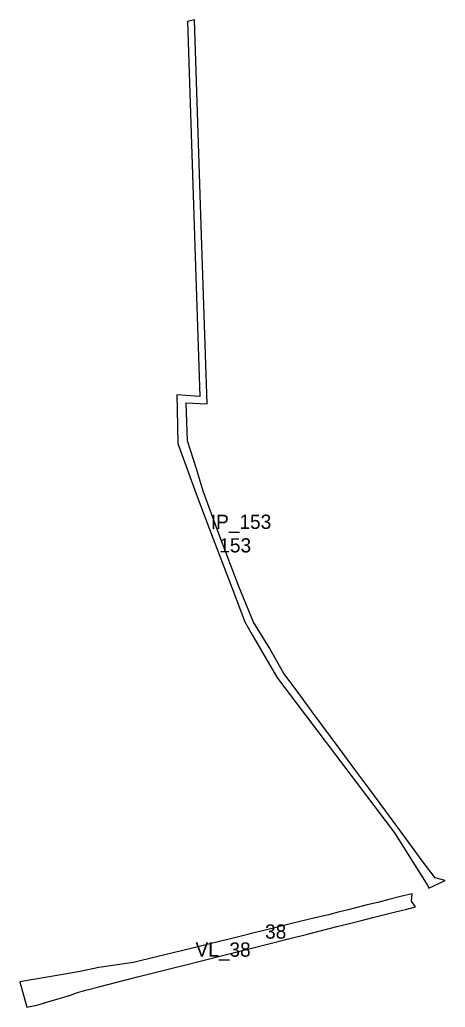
# Model space of a CAD drawing. Extents: x -521939 to -518034, y -1194984 to -1189555.
# Drawn here: x -519208 to -518909, y -1192540 to -1191848 of the extents above; entities that cross this region are included whole.
import ezdxf

# ---------------------------------------------------------------- set-up
doc = ezdxf.new("R2010")
doc.units = 0
doc.layers.add('96120023', color=7, linetype='Continuous')
doc.layers.add('ID VPS', color=7, linetype='Continuous')

msp = doc.modelspace()

# ---------------------------------------------------------------- linework, layer by layer
at = {"layer": '96120023'}
for points in [[(-519085.16, -1191847.79), (-519090.12, -1191848.97)], [(-519090.12, -1191848.97), (-519085.14, -1191999.24), (-519084.89, -1192006.65)], [(-519076.23, -1192117.14), (-519080.14, -1191999.07), (-519085.16, -1191847.79)], [(-519084.89, -1192006.65), (-519081.41, -1192111.82)], [(-519091.16, -1192111.23), (-519097.51, -1192110.84)], [(-519097.51, -1192110.84), (-519097.34, -1192121.07)], [(-519081.41, -1192111.82), (-519091.16, -1192111.23)], [(-519090.14, -1192143.06), (-519091, -1192116.25)], [(-519091, -1192116.25), (-519081.24, -1192116.84)], [(-519097.34, -1192121.07), (-519096.85, -1192144.75)], [(-519081.24, -1192116.84), (-519076.23, -1192117.14)], [(-519079.2, -1192178.33), (-519083.86, -1192162.62), (-519090.14, -1192143.06)], [(-519096.85, -1192144.75), (-519088.41, -1192167.96)], [(-519088.41, -1192167.96), (-519084.92, -1192177.56)], [(-519084.92, -1192177.56), (-519080.59, -1192189.45), (-519072.1, -1192211.71)], [(-519067.32, -1192210.12), (-519079.2, -1192178.33)], [(-519072.1, -1192211.71), (-519059.06, -1192245.89)], [(-519054.11, -1192245.13), (-519067.32, -1192210.12)], [(-519059.06, -1192245.89), (-519049.87, -1192269.96), (-519045.63, -1192277.25)], [(-519043.74, -1192269.98), (-519054.11, -1192245.13)], [(-519032.9, -1192287.75), (-519043.74, -1192269.98)], [(-519045.63, -1192277.25), (-519031.55, -1192301.49)], [(-519022.45, -1192306.15), (-519032.9, -1192287.75)], [(-519031.55, -1192301.49), (-519026.95, -1192309.4)], [(-519026.95, -1192309.4), (-518944.8, -1192417.71)], [(-519012.56, -1192319.48), (-519022.45, -1192306.15)], [(-519002.52, -1192333.06), (-519012.56, -1192319.48)], [(-518982.99, -1192359.44), (-519002.52, -1192333.06)], [(-518972.74, -1192373.31), (-518982.99, -1192359.44)], [(-518962.98, -1192386.51), (-518972.74, -1192373.31)], [(-518950.99, -1192402.69), (-518962.98, -1192386.51)], [(-518934.83, -1192424.56), (-518950.99, -1192402.69)], [(-518944.8, -1192417.71), (-518921.58, -1192455.03)], [(-518925.41, -1192437.29), (-518934.83, -1192424.56)], [(-518909.26, -1192451.23), (-518916.45, -1192449.41), (-518925.41, -1192437.29)], [(-518921.58, -1192455.03), (-518920.67, -1192456.5)], [(-518920.67, -1192456.5), (-518909.26, -1192451.23)], [(-518940.73, -1192462.51), (-518948.86, -1192464.56)], [(-518932.56, -1192460.45), (-518940.73, -1192462.51)], [(-518932.84, -1192465.6), (-518932.56, -1192460.45)], [(-518963.93, -1192468.35), (-518977.36, -1192471.72)], [(-518956.58, -1192466.5), (-518963.93, -1192468.35)], [(-518948.86, -1192464.56), (-518956.58, -1192466.5)], [(-518936.14, -1192471.19), (-518930.23, -1192469.72)], [(-518930.23, -1192469.72), (-518932.84, -1192465.6)], [(-518991.27, -1192475.14), (-518998.5, -1192476.92)], [(-518984.47, -1192473.47), (-518991.27, -1192475.14)], [(-518977.36, -1192471.72), (-518984.47, -1192473.47)], [(-518960.05, -1192477.14), (-518952.49, -1192475.3)], [(-518952.49, -1192475.3), (-518944.06, -1192473.16)], [(-518944.06, -1192473.16), (-518936.14, -1192471.19)], [(-519020.71, -1192482.38), (-519028.71, -1192484.35)], [(-519013.08, -1192480.51), (-519020.71, -1192482.38)], [(-519005.33, -1192478.6), (-519013.08, -1192480.51)], [(-519006, -1192488.76), (-518985.24, -1192483.53)], [(-518998.5, -1192476.92), (-519005.33, -1192478.6)], [(-518985.24, -1192483.53), (-518977.46, -1192481.59)], [(-518977.46, -1192481.59), (-518969.05, -1192479.46)], [(-518969.05, -1192479.46), (-518960.05, -1192477.14)], [(-519051.58, -1192489.98), (-519059.9, -1192492.02)], [(-519043.33, -1192487.95), (-519051.58, -1192489.98)], [(-519028.71, -1192484.35), (-519043.33, -1192487.95)], [(-519020.11, -1192492.23), (-519006, -1192488.76)], [(-519077.24, -1192496.29), (-519085.55, -1192498.33)], [(-519059.9, -1192492.02), (-519077.24, -1192496.29)], [(-519043.04, -1192498.09), (-519033.96, -1192495.77)], [(-519033.96, -1192495.77), (-519020.11, -1192492.23)], [(-519094.37, -1192500.5), (-519111.71, -1192504.77)], [(-519085.55, -1192498.33), (-519094.37, -1192500.5)], [(-519081.2, -1192507.68), (-519060.87, -1192502.57)], [(-519060.87, -1192502.57), (-519043.04, -1192498.09)], [(-519127.99, -1192508.77), (-519152.33, -1192512.23), (-519166.59, -1192515.29), (-519207.76, -1192522.22)], [(-519111.71, -1192504.77), (-519127.99, -1192508.77)], [(-519097.19, -1192511.77), (-519090.36, -1192509.99)], [(-519090.36, -1192509.99), (-519081.2, -1192507.68)], [(-519125.24, -1192518.78), (-519097.19, -1192511.77)], [(-519207.76, -1192522.22), (-519202.8, -1192540.04)], [(-519152.38, -1192525.82), (-519125.24, -1192518.78)], [(-519185.81, -1192535.58), (-519172.77, -1192531.87)], [(-519172.77, -1192531.87), (-519167.2, -1192529.66), (-519163.86, -1192528.76)], [(-519163.86, -1192528.76), (-519161.28, -1192528.12)], [(-519161.28, -1192528.12), (-519152.38, -1192525.82)], [(-519202.8, -1192540.04), (-519195.88, -1192538.48), (-519185.81, -1192535.58)]]:
    msp.add_lwpolyline(points, dxfattribs=at)

# ---------------------------------------------------------------- texts
for s, p in [('IP_153', (-519073.72, -1192204.71)), ('VL_38', (-519084.44, -1192504.6))]:
    msp.add_text(s, height=10, rotation=0, dxfattribs=at).set_placement(p)
at = {"layer": 'ID VPS'}
for s, rotation, p in [('153', 360, (-519067.76, -1192221.23)), ('38', 0, (-519035.64, -1192491.96))]:
    msp.add_text(s, height=10, rotation=rotation, dxfattribs=at).set_placement(p)

doc.saveas('drawing.dxf')
